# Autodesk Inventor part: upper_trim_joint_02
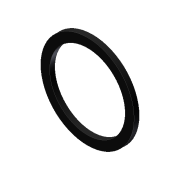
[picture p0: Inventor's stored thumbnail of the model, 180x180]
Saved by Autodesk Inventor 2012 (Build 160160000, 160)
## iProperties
Created: 2002-07
Part Number: upper_trim_joint_02
Document SubType Name: Modeling
Designer: Lieven Grauls
Stock Number: upper_trim_joint_02
Project: Valve Techcamp 2008
Density: 1 g/cm^3
Mass: 4.57881 g
Surface Area: 36.5406 cm^2
Volume: 4.57881 cm^3
Material: Default
Company: Autodesk
Control State: 0
Master: False
Checked Out: False
Shininess: 64.0
Length Units: 11269
Angle Units: 11279
Time Units: 11290
Mass Units: 11283
Length Display Precision: 3
Angle Display Precision: 2
Density: 0.0
Volumn: 0.0
Area: 0.0
PropertySet Name: Model Information
Author: Lieven Grauls
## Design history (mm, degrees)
sketch "Sketch1"
  geometry: L1 (29.5, 0)-(36.5, 0); L2 (36.5, 0)-(36.5, 4); L3 (36.5, 4)-(29.5, 4); L4 (29.5, 4)-(29.5, 0); L5 (0, 4.8)-(0, -0.8) reference; 1 further point
  constraints: 8 end point, 2 parallel, 1 horizontal, 1 horizontal alignment, 1 perpendicular
  dimensions: "d0" = 59 diameter of L4 L5; "d1" = 73 diameter of L2 L5; "d2" = 4 distance between parallel lines of L1 L3
revolve "Revolution1" sketch "Sketch1" stored, may be unused: angle "d3" = 90 deg
sketch "Sketch2"
  geometry: L1 (0, 51.715)-(0, -54.791) reference; L2 (51.1, 0)-(-51.1, 0) reference; L3 (0, 0)-(4, -29.228); L4 (0, 0)-(29.228, -4); L5 (4, -29.228)-(4, -36.28); L6 (29.228, -4)-(36.28, -4); A1 r 36.5 centre (0, 0) between (31.61, -18.25) and (4, -36.28) reference; A2 r 36.5 centre (0, 0) between (4, -36.28) and (31.61, -18.25); A3 r 29.5 centre (0, 0) between (4, -29.228) and (29.228, -4) reference
  constraints: 8 end point, 7 point on circle, 2 perpendicular, 1 centre point, 1 coincident
  dimensions: "d10" = 4 distance between parallel lines of L5 L1; "d11" = 4 distance between parallel lines of L2 L6
extrude "Extrusion1" cut sketch "Sketch2" stored distance "d6" = 10; taper "d7" = 0 deg
node "Volumenkörper1"
node "Volumenkörpern"
node "Oberflächenkörpern"
